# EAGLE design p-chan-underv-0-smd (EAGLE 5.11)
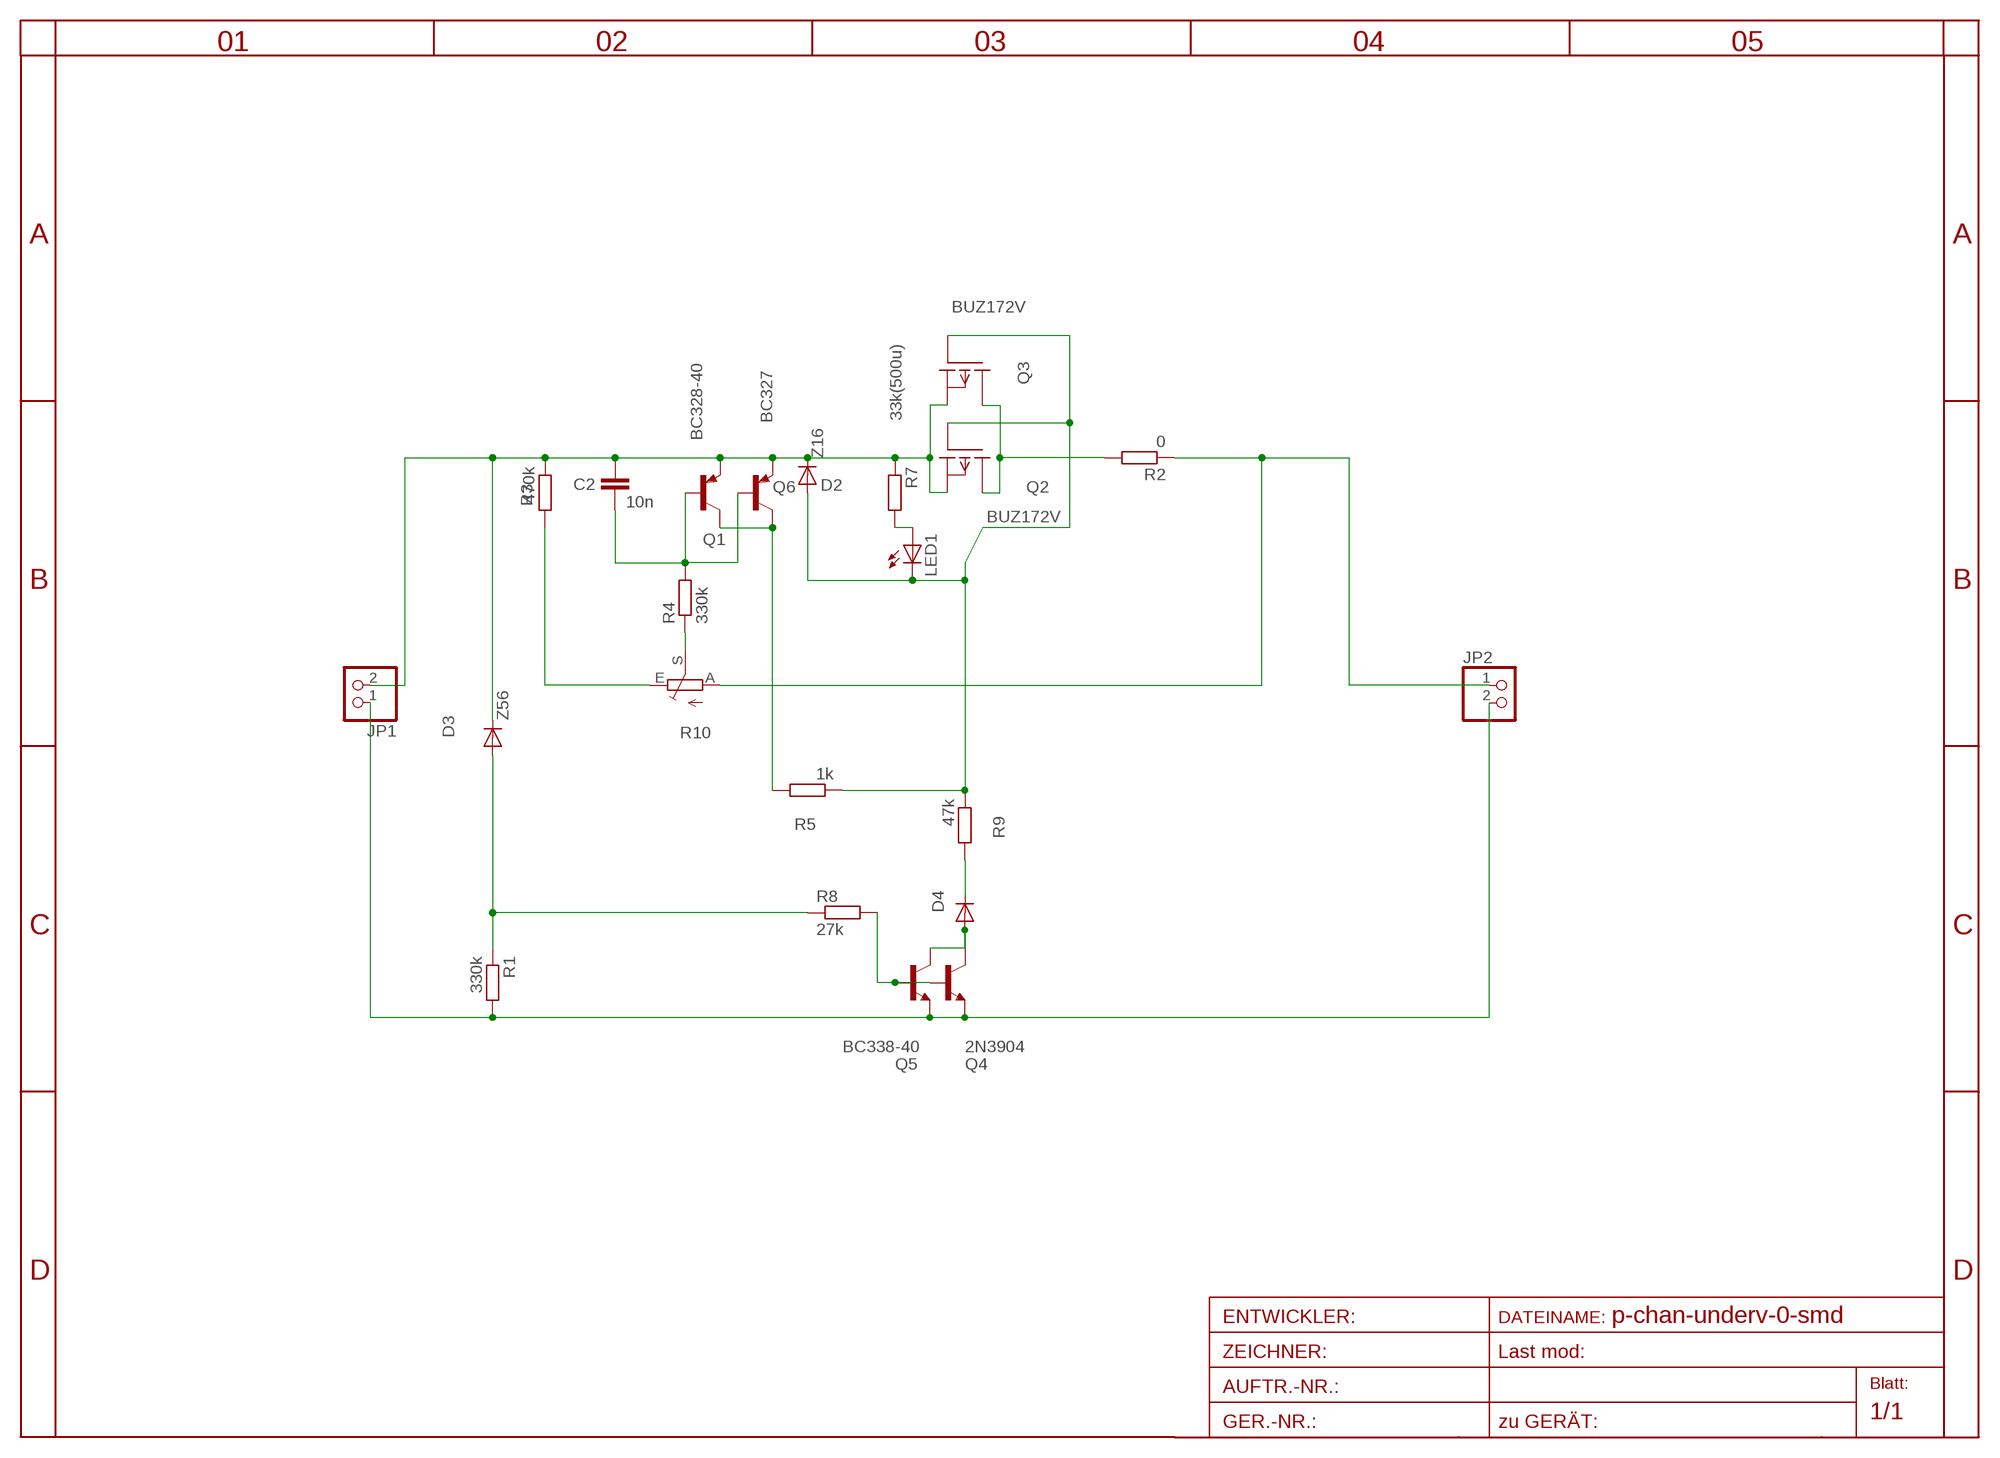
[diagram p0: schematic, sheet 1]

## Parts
C2  10n  C-EU025-024X044  [C025-024X044]
D2  Z16  DIODE-D-7.5  [D-7.5]
D3  Z56  DIODE-D-7.5  [D-7.5]
D4  DIODE-D-7.5  [D-7.5]
JP1  PINHD-1X2  [1X02]
JP2  PINHD-1X2  [1X02]
LED1  LED3MM  [LED3MM]
Q1  BC328-40  [TO92-EBC]
Q2  BUZ172V  [TO220V]
Q3  BUZ172V  [TO220V]
Q4  2N3904  [TO92]
Q5  BC338-40  [TO92-EBC]
Q6  BC327  [TO92]
R1  330k  R-EU_0204/7  [0204/7]
R2  0  R-EU_0204/5  [0204/5]
R3  470k  R-EU_0204/5  [0204/5]
R4  330k  R-EU_0204/7  [0204/7]
R5  1k  R-EU_0207/40  [0207/40]
R7  33k(500u)  R-EU_0204/7  [0204/7]
R8  27k  R-EU_0204/7  [0204/7]
R9  47k  R-EU_0204/5  [0204/5]
R10  TRIM_EU-EVND_H  [EVND8AA]

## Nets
B-Q1: C2.2 Q1.B Q6.2(B) R4.2
C-Q1: Q1.C Q6.3(C) R5.2
C-Q4: D4.A Q4.1(C) Q5.C
GATE: D2.A LED1.K(C) Q2.1(G) Q3.1(G) R5.1 R9.1
N$3: LED1.A R7.2
N$4: R4.1 R10.S
N$5: D3.A R1.1 R8.1
N$6: R3.2 R10.E
N$9: Q2.2(D) Q3.2(D) R2.2
N$13: Q4.2(B) Q5.B R8.2
N$15: D4.C R9.2
V+IN: C2.1 D2.C D3.C JP1.2 Q1.E Q2.3(S) Q3.3(S) Q6.1(E) R3.1 R7.1
V+OUT: JP2.1 R2.1 R10.A
V-: JP1.1 JP2.2 Q4.3(E) Q5.E R1.2

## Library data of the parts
C2 = rcl-2:C-EU: CAPACITOR, European symbol
D2-D4 = diode-1:DIODE-: DIODE
JP1 JP2 = pinhead:PINHD-1X2: PIN HEADER
LED1 = led:LED: LED
Q1 = transistor-pnp:BC328*: PNP Transistror
Q2 Q3 = transistor-fet:BUZ172: P-Channel Enhancement MOSFET -100V; -5A; 0,8Ohm
Q4 = transistor-npn:2N3904: NPN Transistor
Q5 = transistor-npn:BC338*: NPN Transistor
Q6 = transistor-pnp:BC327: PNP Transistor
R1-R5 R7-R9 = rcl-2:R-EU_: RESISTOR, European symbol
R10 = pot:TRIM_EU-: POTENTIOMETER

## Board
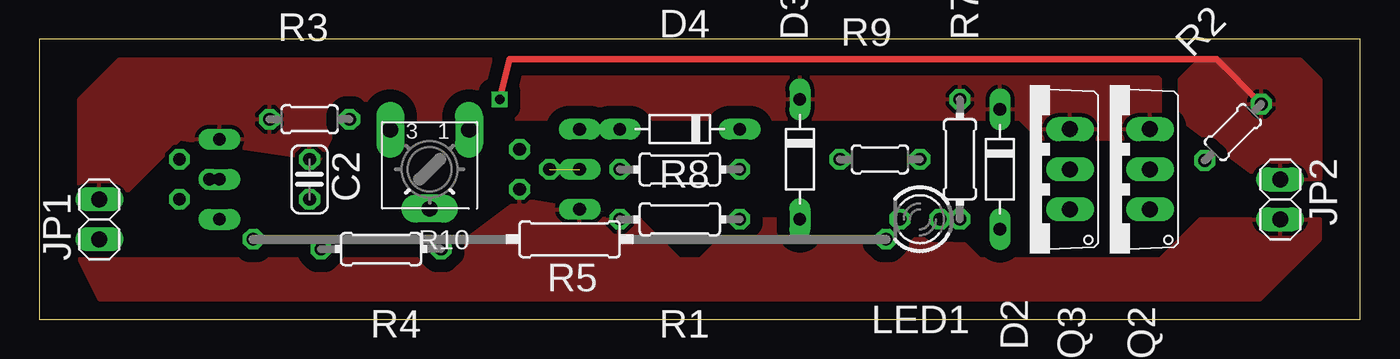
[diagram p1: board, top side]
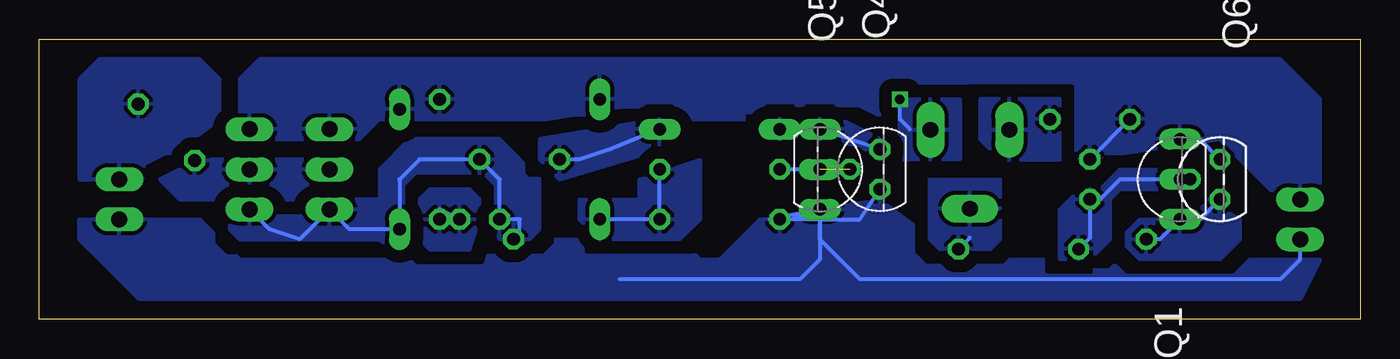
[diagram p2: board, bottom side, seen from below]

Size 83.82 x 17.78 mm. Coordinates in mm from the lower left corner, seen from the top.
Outline: 0,0 83.82,0 83.82,17.78 0,17.78 0,0
Copper layers (1*16): Top 0.035mm / dielectric 1.5mm / Bottom 0.035mm
Design rules "default": minimum track width 10mil, minimum drill 24mil, track to track 8mil, track to pad 8mil, pad to pad 8mil, via to via 8mil, smd to smd 8mil, copper to edge 40mil, drill to drill 8mil, minimum pad ring 10mil, minimum via ring 8mil, stop-mask expansion 4mil, vias tented up to drill 0mil, thermal gap 10mil

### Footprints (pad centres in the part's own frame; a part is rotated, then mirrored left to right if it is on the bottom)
C025-024X044 = drill 0.813 octagon: 1 -1.27,0; 2 1.27,0
D-7.5 = drill 0.813 long: A 3.81,0; C -3.81,0
1X02 = drill 1.016 long: 1 -1.27,0; 2 1.27,0
LED3MM = drill 0.813 octagon: A -1.27,0; K 1.27,0
TO92-EBC = drill 0.813 long: B 0,-1.27; C -2.54,-1.27; E 2.54,-1.27
TO220V = drill 1.016 long: 1 -2.54,-2.54; 2 0,-2.54; 3 2.54,-2.54
TO92 = drill 0.813 octagon: 1 1.27,0; 2 0,1.905; 3 -1.27,0
0204/7 = drill 0.813 octagon: 1 -3.81,0; 2 3.81,0
0204/5 = drill 0.813 octagon: 1 -2.54,0; 2 2.54,0
0207/40 = drill 0.813 octagon: 1 -20.08,0; 2 20.08,0
EVND8AA = drill 1 pad 1.778 long: A -2.5,-2.5; E 2.5,-2.5; S 0,2.5

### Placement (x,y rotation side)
C2  17.14,8.89 270 top
D2  60.96,9.53 270 top
D3  48.26,10.16 270 top
D4  40.64,12.06 180 top
JP1  3.81,6.35 90 top
JP2  78.74,7.62 270 top
LED1  55.88,6.35 180 top
Q1  12.7,8.89 90 bottom
Q2  67.94,9.53 90 top
Q3  62.87,9.53 90 top
Q4  30.48,9.53 90 bottom
Q5  33.02,9.53 270 bottom
Q6  8.89,8.89 90 bottom
R1  40.64,6.35 180 top
R2  75.75,11.88 225 top
R3  17.14,12.7 0 top
R4  21.68,4.45 180 top
R5  33.66,5.08 180 top
R7  58.42,10.16 270 top
R8  40.64,9.53 180 top
R9  53.34,10.16 180 top
R10  24.77,9.53 180 top

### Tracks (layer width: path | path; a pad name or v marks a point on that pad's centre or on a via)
B-Q1
  Bottom 0.254: Q6.2 Q1.B 15.24,8.89 16.51,7.62 C2.2 17.14,5.18 R4.2
  pour Bottom (isolate 0.813, rank 2): 19.05,3.81 19.05,6.99 17.78,8.26 16.51,8.26 15.24,9.53 12.06,9.53 12.06,8.26 15.24,8.26 15.88,7.62 15.88,5.08 17.14,3.81
C-Q1
  Bottom 0.254: Q6.3 10.16,6.35 Q1.C 12.7,5.08 R5.2
  pour Bottom (isolate 0.813, rank 4): 7.62,6.35 7.62,5.08 8.89,3.81 13.97,3.81 15.24,5.08 13.97,6.35 10.79,6.35 9.53,7.62
C-Q4
  Bottom 0.254: D4.A Q5.C Q4.1
  pour Bottom (isolate 0.813): 30.48,11.43 33.02,12.7 38.1,12.7 38.1,11.43 33.02,11.43 30.48,10.16
GATE
  Bottom 0.254: R5.1 53.34,5.47 53.34,6.35 LED1.K 54.61,8.89 R9.1 59.69,10.16 60.96,8.89 D2.A 64.14,5.71 Q3.1 67.31,5.08 69.22,5.71 Q2.1
  pour Bottom (isolate 0.813, rank 2): 54.61,5.08 52.7,5.08 52.07,5.71 52.07,8.89 54.61,11.43 60.33,11.43 62.23,9.53 62.23,7.62 71.12,7.62 71.75,6.99 71.75,5.71 71.12,5.08 62.23,5.08 61.59,4.45 59.69,6.35 59.69,8.26 55.88,8.26
N$3
  Bottom 0.254: LED1.A 58.42,6.99 R7.2
  pour Bottom (isolate 0.813): 55.88,6.35 55.88,7.62 56.52,8.26 59.05,8.26 59.69,7.62 59.69,5.08 59.05,4.45 56.52,4.45
N$4
  Bottom 0.254: R4.1 24.77,5.18
  pour Bottom (isolate 0.813, rank 3): 22.86,8.89 22.86,5.08 23.5,4.45 26.67,4.45 27.3,5.08 27.3,8.89
N$5
  Bottom 0.254: R8.1 R1.1 D3.A
  pour Bottom (isolate 0.813, rank 2): 41.91,10.16 41.91,6.35 43.18,5.08 48.26,5.08 49.53,6.35 49.53,7.62 45.72,7.62 45.72,8.89
N$6
  pour Bottom (isolate 0.813, rank 3): 19.05,13.97 24.13,13.97 24.13,11.43 22.86,10.16 19.05,10.16
N$9
  pour Bottom (isolate 0.813): 66.04,10.16 73.66,10.16 76.2,8.89 74.93,7.62 67.31,7.62 66.04,8.89
N$13  (1 unrouted)
  Bottom 0.254: Q5.B R8.2
N$15
  Bottom 0.254: D4.C 47.62,10.79 49.53,10.16 R9.2
  pour Bottom (isolate 0.813): 44.45,12.7 52.07,11.43 52.07,10.16 50.8,8.89 44.45,10.79
V+IN
  Bottom 0.254: Q6.1 10.16,11.43 Q1.E | C2.1 R3.1
  pour Bottom (isolate 0.813, rank 5): 2.54,7.62 2.54,13.97 5.08,16.51 69.85,16.51 71.12,15.24 71.12,12.7 69.85,11.43 63.5,11.43 62.23,12.7 19.05,12.7 17.78,10.16 8.89,11.43 5.08,7.62
  pour Top (isolate 0.813, rank 5): 2.54,7.62 2.54,13.97 5.08,16.51 69.85,16.51 71.12,15.24 71.12,12.7 69.85,11.43 63.5,11.43 62.23,12.7 19.05,12.7 17.78,10.16 8.89,11.43 5.08,7.62
V+OUT  (via drill 0.6)
  Top 0.406: v29.21,13.97 29.84,16.51 74.71,16.51 R2.1
  Bottom 0.254: 28.57,12.06 29.21,12.7 v29.21,13.97
  pour Bottom (isolate 0.813, rank 5): 72.39,12.7 72.39,15.24 73.66,16.51 80.01,16.51 81.28,15.24 81.28,8.89 77.47,8.89
  pour Bottom (isolate 0.813, rank 3): 25.4,13.97 25.4,10.16 29.21,10.16 29.21,13.97
  pour Top (isolate 0.813, rank 5): 72.39,12.7 72.39,15.24 73.66,16.51 80.01,16.51 81.28,15.24 81.28,8.89 77.47,8.89
V-
  Bottom 0.254: JP1.1 3.81,3.81 5.08,2.54 31.75,2.54 34.29,5.08 34.29,6.35 | 34.29,6.35 36.2,6.35 Q5.E 37.47,6.35 R1.2 | 34.29,6.35 34.29,3.81 35.56,2.54 46.99,2.54 | Q4.3 31.75,6.35 34.29,6.35
  pour Bottom (isolate 0.813, rank 5): 2.54,3.81 3.81,1.27 77.47,1.27 81.28,5.08 81.28,6.35 73.66,6.35 71.12,3.81 59.69,3.81 58.42,5.08 48.26,5.08 46.99,6.35 44.45,6.35 41.91,3.81 40.64,3.81 38.1,6.35 30.48,7.62 25.4,3.81
  pour Top (isolate 0.813, rank 5): 2.54,3.81 3.81,1.27 77.47,1.27 81.28,5.08 81.28,6.35 73.66,6.35 71.12,3.81 59.69,3.81 58.42,5.08 48.26,5.08 46.99,6.35 44.45,6.35 41.91,3.81 40.64,3.81 38.1,6.35 30.48,7.62 25.4,3.81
